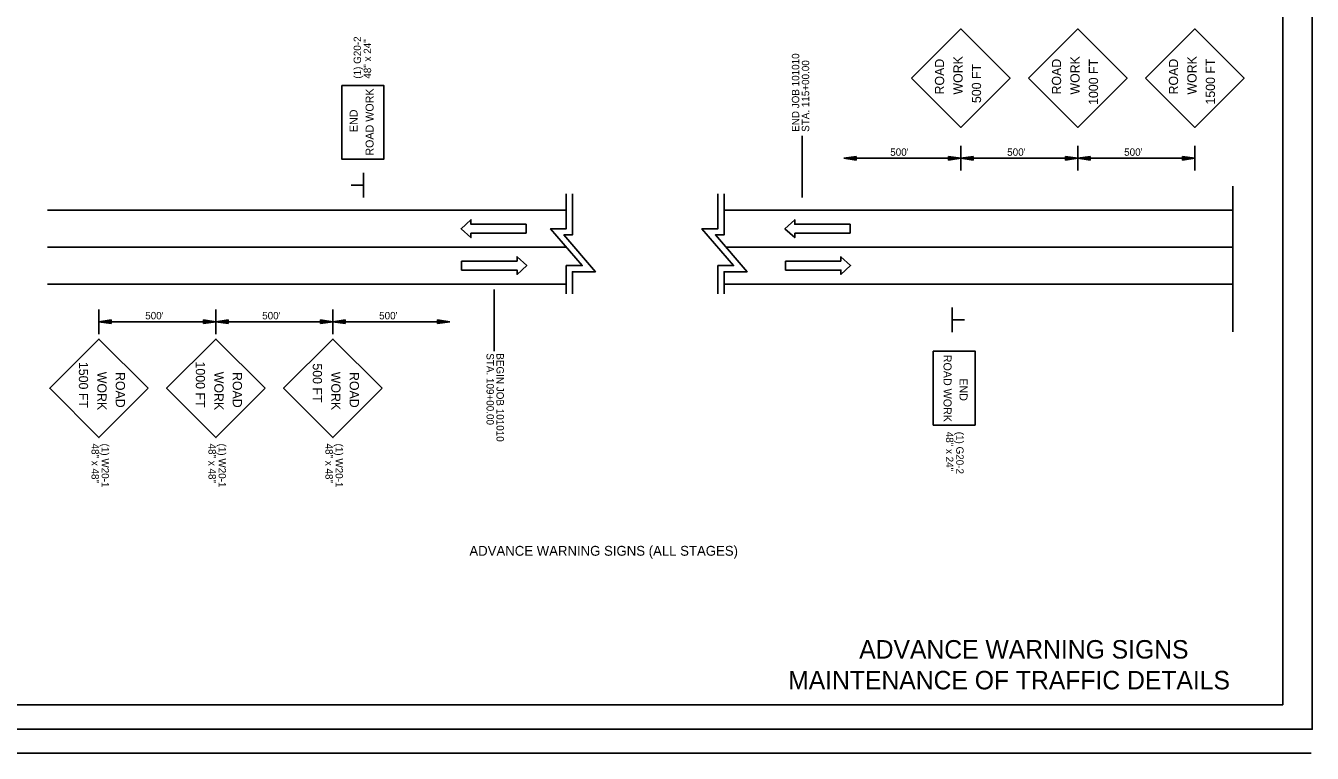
# Model space of a CAD drawing. Extents: x 6125 to 14104, y 8730 to 11067.
# Drawn here: x 6841 to 7886, y 9961 to 10551 of the extents above; entities that cross this region are included whole.
import ezdxf

# ---------------------------------------------------------------- set-up
doc = ezdxf.new("R2010")
doc.units = 0
for name, color, linetype in [('GREEN_TXT', 7, 'Continuous'), ('R_MOT Stage 3', 7, 'Continuous'), ('R_Signs', 7, 'Continuous'), ('SEAL-INFO', 7, 'Continuous'), ('Stage 1 Construction', 7, 'Continuous')]:
    doc.layers.add(name, color=color, linetype=linetype)

# ---------------------------------------------------------------- blocks, each defined once
blk = doc.blocks.new('ARROW')
at = {"layer": 'R_Signs'}
for p, q in [((-2, 0.3), (0, 0)), ((-2, 0.3), (-2, -0.3)), ((-2, 0.25), (-0.334, 0)), ((-2, 0.199), (-0.678, 0)), ((-2, 0.149), (-1.011, 0)), ((-2, 0.097), (-1.35, 0)), ((-2, 0.047), (-1.684, 0)), ((-2, -0.3), (0, 0)), ((-2, -0.098), (-1.35, 0)), ((-2, -0.199), (-0.678, 0)), ((-2, -0.25), (-0.334, 0)), ((-2, -0.149), (-1.011, 0)), ((-2, -0.047), (-1.684, 0))]:
    blk.add_line(p, q, dxfattribs=at)

msp = doc.modelspace()

# ---------------------------------------------------------------- linework, layer by layer
for p, q in [((7471.8, 10462), (7471.8, 10412)), ((7600.8, 10433.8), (7600.8, 10453.8)), ((7695.8, 10433.8), (7695.8, 10453.8)), ((7790.8, 10433.8), (7790.8, 10453.8)), ((7600.8, 10443.8), (7505.8, 10443.8)), ((7600.8, 10443.8), (7590.8, 10443.8)), ((7695.8, 10443.8), (7600.8, 10443.8)), ((7695.8, 10443.8), (7685.8, 10443.8)), ((7790.8, 10443.8), (7695.8, 10443.8)), ((7790.8, 10443.8), (7780.8, 10443.8)), ((7115.5, 10412), (7115.5, 10432)), ((7115.5, 10422), (7105.5, 10422)), ((6858.9, 10401.6), (7280.3, 10401.6)), ((7408.4, 10401.6), (7821.8, 10401.6)), ((6858.9, 10371.6), (7280.3, 10371.6)), ((7410, 10371.6), (7821.8, 10371.6)), ((6858.9, 10341.6), (7280.3, 10341.6)), ((7221.6, 10337.1), (7221.6, 10287.1)), ((7408.4, 10341.6), (7821.8, 10341.6)), ((6900.7, 10301), (6900.7, 10321)), ((6995.7, 10301), (6995.7, 10321)), ((7090.7, 10301), (7090.7, 10321)), ((7593.8, 10302.6), (7593.8, 10322.6)), ((6900.7, 10311), (6995.7, 10311)), ((6900.7, 10311), (6910.7, 10311)), ((6995.7, 10311), (7090.7, 10311)), ((6995.7, 10311), (7005.7, 10311)), ((7090.7, 10311), (7100.7, 10311)), ((7090.7, 10311), (7185.7, 10311)), ((7593.8, 10312.6), (7603.8, 10312.6))]:
    msp.add_line(p, q)
for points in [[(7560.8, 10508.8), (7600.8, 10548.8), (7640.8, 10508.8), (7600.8, 10468.8)], [(7655.8, 10508.8), (7695.8, 10548.8), (7735.8, 10508.8), (7695.8, 10468.8)], [(7750.8, 10508.8), (7790.8, 10548.8), (7830.8, 10508.8), (7790.8, 10468.8)], [(7098.1, 10503), (7132.1, 10503), (7132.1, 10443), (7098.1, 10443)], [(6940.7, 10257), (6900.7, 10217), (6860.7, 10257), (6900.7, 10297)], [(7035.7, 10257), (6995.7, 10217), (6955.7, 10257), (6995.7, 10297)], [(7130.7, 10257), (7090.7, 10217), (7050.7, 10257), (7090.7, 10297)], [(7612.5, 10227.1), (7578.4, 10227.1), (7578.4, 10287.1), (7612.5, 10287.1)]]:
    msp.add_lwpolyline(points, close=True)
for points in [[(7280.3, 10414.8), (7280.3, 10386.6), (7267.5, 10386.6), (7293.2, 10356.6), (7280.3, 10356.6), (7280.3, 10333.7)], [(7285.3, 10414.8), (7285.3, 10381.6), (7278.4, 10381.6), (7304, 10351.6), (7285.3, 10351.6), (7285.3, 10333.7)], [(7403.4, 10414.8), (7403.4, 10386.6), (7390.5, 10386.6), (7416.2, 10356.6), (7403.4, 10356.6), (7403.4, 10333.7)], [(7408.4, 10414.8), (7408.4, 10381.6), (7401.4, 10381.6), (7427.1, 10351.6), (7408.4, 10351.6), (7408.4, 10333.7)]]:
    msp.add_lwpolyline(points)
at = {"layer": 'GREEN_TXT'}
for p, q in [((7862.4, 10000), (7862.4, 11027.3)), ((7862.4, 10000), (6281.5, 10000)), ((6125.4, 9960.6), (7885.4, 9960.6))]:
    msp.add_line(p, q, dxfattribs=at)
at = {"layer": 'R_MOT Stage 3'}
msp.add_line((7821.8, 10421.1), (7821.8, 10302.9), dxfattribs=at)
at = {"layer": 'SEAL-INFO'}
msp.add_lwpolyline([(6219.5, 11046.8), (7886.2, 11046.8), (7886.2, 9980.1), (6219.5, 9980.1)], close=True, dxfattribs=at)
at = {"layer": 'Stage 1 Construction'}
for p, q in [((7247.7, 10383), (7202.8, 10383)), ((7510.8, 10383), (7465.8, 10383)), ((7195.3, 10360.2), (7240.3, 10360.2)), ((7458.4, 10360.2), (7503.3, 10360.2))]:
    msp.add_line(p, q, dxfattribs=at)
for points in [[(7247.7, 10383), (7247.7, 10390.2), (7202.8, 10390.2), (7202.8, 10393.8), (7194.9, 10386.6), (7202.8, 10379.4), (7202.8, 10383)], [(7510.8, 10383), (7510.8, 10390.2), (7465.8, 10390.2), (7465.8, 10393.8), (7457.9, 10386.6), (7465.8, 10379.4), (7465.8, 10383)], [(7195.3, 10360.2), (7195.3, 10353), (7240.3, 10353), (7240.3, 10349.4), (7248.2, 10356.6), (7240.3, 10363.8), (7240.3, 10360.2)], [(7458.4, 10360.2), (7458.4, 10353), (7503.3, 10353), (7503.3, 10349.4), (7511.2, 10356.6), (7503.3, 10363.8), (7503.3, 10360.2)]]:
    msp.add_lwpolyline(points, dxfattribs=at)

# ---------------------------------------------------------------- block references
at = {"xscale": 5, "rotation": 180}
for p, yscale in [((7505.8, 10443.8), -5), ((7600.8, 10443.8), -5), ((7600.8, 10443.8), -5), ((7695.8, 10443.8), -5), ((7695.8, 10443.8), -5), ((6900.7, 10311), 5), ((6900.7, 10311), 5), ((6995.7, 10311), 5), ((6995.7, 10311), 5), ((7090.7, 10311), 5)]:
    msp.add_blockref('ARROW', p, dxfattribs=dict(at, yscale=yscale))
at = {"xscale": 5}
for p, yscale in [((7600.8, 10443.8), -5), ((7695.8, 10443.8), -5), ((7695.8, 10443.8), -5), ((7790.8, 10443.8), -5), ((7790.8, 10443.8), -5), ((6995.7, 10311), 5), ((6995.7, 10311), 5), ((7090.7, 10311), 5), ((7090.7, 10311), 5), ((7185.7, 10311), 5)]:
    msp.add_blockref('ARROW', p, dxfattribs=dict(at, yscale=yscale))

# ---------------------------------------------------------------- texts
for s, height, rotation, p in [('(1) G20-2', 6, 90, (7113.6, 10508.4)), ('48" x 24"', 6, 90, (7121.8, 10508.4)), ('END JOB 101010', 6, 90, (7469.5, 10465.2)), ('STA. 115+00.00', 6, 90, (7477.6, 10465.2)), ('ROAD', 7.5, 90, (7587.2, 10495.6)), ('WORK', 7.5, 90, (7602.2, 10495.5)), ('ROAD', 7.5, 90, (7682.2, 10495.6)), ('WORK', 7.5, 90, (7697.2, 10495.5)), ('1000 FT', 7.5, 90, (7712.2, 10487.1)), ('ROAD', 7.5, 90, (7777.2, 10495.6)), ('WORK', 7.5, 90, (7792.2, 10495.5)), ('1500 FT', 7.5, 90, (7807.2, 10487.4)), ('500 FT', 7.5, 90, (7617.2, 10488.6)), ('ROAD WORK', 6.5, 90, (7123.8, 10445.9)), ('END', 6.5, 90, (7110.8, 10465)), ('STA. 109+00.00', 6, 270, (7215.5, 10285.4)), ('BEGIN JOB 101010', 6, 270, (7223.6, 10285.4)), ('ROAD WORK', 6.5, 270, (7586.7, 10284.2)), ('1500 FT', 7.5, 270, (6884.4, 10278.4)), ('1000 FT', 7.5, 270, (6979.4, 10278.7)), ('500 FT', 7.5, 270, (7074.4, 10277.2)), ('WORK', 7.5, 270, (6899.4, 10270.4)), ('ROAD', 7.5, 270, (6914.4, 10270.2)), ('WORK', 7.5, 270, (6994.4, 10270.4)), ('ROAD', 7.5, 270, (7009.4, 10270.2)), ('WORK', 7.5, 270, (7089.4, 10270.4)), ('ROAD', 7.5, 270, (7104.4, 10270.2)), ('END', 6.5, 270, (7599.7, 10265.1)), ('48" x 24"', 6, 270, (7588.7, 10221.7)), ('(1) G20-2', 6, 270, (7597, 10221.7)), ('48" x 48"', 6, 270, (6894.7, 10212.1)), ('(1) W20-1', 6, 270, (6902.9, 10212.1)), ('48" x 48"', 6, 270, (6989.7, 10212.1)), ('(1) W20-1', 6, 270, (6997.9, 10212.1)), ('48" x 48"', 6, 270, (7084.7, 10212.1)), ('(1) W20-1', 6, 270, (7092.9, 10212.1))]:
    msp.add_text(s, height=height, rotation=rotation).set_placement(p)
for s, height, p in [("500'", 6, (7543.4, 10445.8)), ("500'", 6, (7638.4, 10445.8)), ("500'", 6, (7733.4, 10445.8)), ("500'", 6, (6938.3, 10313)), ("500'", 6, (7033.3, 10313)), ("500'", 6, (7128.3, 10313)), ('ADVANCE WARNING SIGNS (ALL STAGES)', 8, (7201.6, 10121))]:
    msp.add_text(s, height=height).set_placement(p)
at = {"layer": 'GREEN_TXT'}
for s, p in [('ADVANCE WARNING SIGNS', (7518.2, 10037.5)), ('MAINTENANCE OF TRAFFIC DETAILS', (7460.5, 10012.5))]:
    msp.add_text(s, height=15, dxfattribs=at).set_placement(p)

doc.saveas('drawing.dxf')
